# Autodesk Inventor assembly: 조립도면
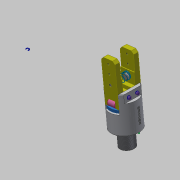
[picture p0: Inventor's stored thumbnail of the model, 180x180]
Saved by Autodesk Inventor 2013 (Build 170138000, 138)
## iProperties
Created: 2019-02
Part Number: 조립도면
Document SubType Name: Assembly
Designer: Gpr
Author: Gpr
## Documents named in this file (11)
- C:\Users\Administrator\Desktop\490207V1021\조립도면.iam
- C:\Users\Administrator\Desktop\490207V1021\본체.ipt
- C:\Users\Administrator\Desktop\490207V1021\E-링.ipt
- C:\Users\Administrator\Desktop\490207V1021\O-링.ipt
- C:\Users\Administrator\Desktop\490207V1021\가이드핀.ipt
- C:\Users\Administrator\Desktop\490207V1021\부시.ipt
- C:\Users\Administrator\Desktop\490207V1021\스프링.ipt
- C:\Users\Administrator\Desktop\490207V1021\평행핀 6x28.ipt
- C:\Users\Administrator\Desktop\490207V1021\피스톤.ipt
- C:\Users\Administrator\Desktop\490207V1021\핀.ipt
- C:\Users\Administrator\Desktop\490207V1021\핑거.ipt
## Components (13 placed, 6 different names)
1. E-링:1
2. O-링:1
3. 가이드핀:1
4. 피스톤:1
5. 핀:1
6. 핑거:1
7. O-링:2
8. 핑거:2
9. 핀:2
10. 가이드핀:2
11. E-링:2
12. E-링:3
13. E-링:4
